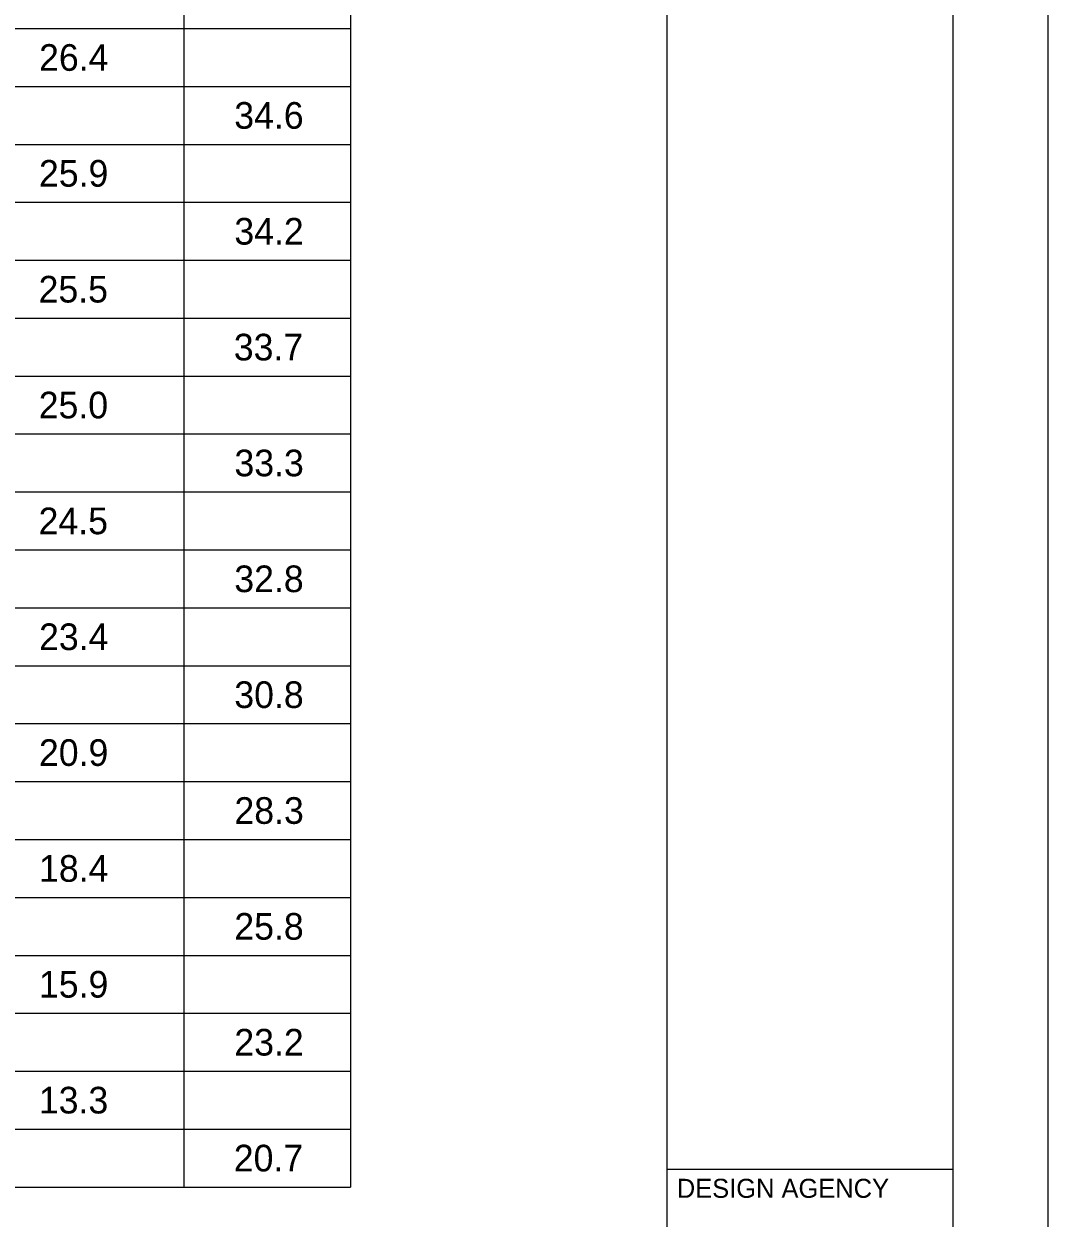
# Model space of a CAD drawing. Extents: x 0 to 34, y 0 to 22.
# Drawn here: x 28.62 to 34, y 4.24 to 10.52 of the extents above; entities that cross this region are included whole.
import ezdxf

# ---------------------------------------------------------------- set-up
doc = ezdxf.new("R2010")
doc.units = 0
for name, color, linetype in [('BR_P_Gen_Text', 7, 'Continuous'), ('SH_Border', 7, 'Continuous'), ('SH_Cut_Line', 7, 'Continuous'), ('SH_Data', 7, 'Continuous')]:
    doc.layers.add(name, color=color, linetype=linetype)

msp = doc.modelspace()

# ---------------------------------------------------------------- linework, layer by layer
at = {"layer": 'BR_P_Gen_Text'}
for p, q in [((30.3354, 21.1204), (30.3354, 4.4066)), ((29.4604, 20.7019), (29.4604, 4.4066)), ((22.1053, 10.4936), (30.3354, 10.4936)), ((22.1053, 10.1893), (30.3354, 10.1893)), ((22.1053, 9.8849), (30.3354, 9.8849)), ((22.1053, 9.5806), (30.3354, 9.5806)), ((22.1053, 9.2762), (30.3354, 9.2762)), ((22.1053, 8.9719), (30.3354, 8.9719)), ((22.1053, 8.6675), (30.3354, 8.6675)), ((22.1053, 8.3632), (30.3354, 8.3632)), ((22.1053, 8.0588), (30.3354, 8.0588)), ((22.1053, 7.7545), (30.3354, 7.7545)), ((22.1053, 7.4501), (30.3354, 7.4501)), ((22.1053, 7.1458), (30.3354, 7.1458)), ((22.1053, 6.8414), (30.3354, 6.8414)), ((22.1053, 6.5371), (30.3354, 6.5371)), ((22.1053, 6.2327), (30.3354, 6.2327)), ((22.1053, 5.9284), (30.3354, 5.9284)), ((22.1053, 5.624), (30.3354, 5.624)), ((22.1053, 5.3197), (30.3354, 5.3197)), ((22.1053, 5.0153), (30.3354, 5.0153)), ((22.1053, 4.711), (30.3354, 4.711)), ((22.1053, 4.4066), (30.3354, 4.4066))]:
    msp.add_line(p, q, dxfattribs=at)
at = {"layer": 'SH_Border'}
for p, q in [((32, 0.5), (32, 21.5)), ((32, 4.5), (33.5, 4.5))]:
    msp.add_line(p, q, dxfattribs=at)
msp.add_lwpolyline([(1.5, 21.5), (33.5, 21.5), (33.5, 0.5), (1.5, 0.5)], close=True, dxfattribs=at)
at = {"layer": 'SH_Cut_Line'}
msp.add_lwpolyline([(0, 0), (34, 0), (34, 22), (0, 22)], close=True, dxfattribs=at)

# ---------------------------------------------------------------- texts
at = {"layer": 'BR_P_Gen_Text'}
for s, p in [('26.4', (28.7005, 10.2714)), ('34.6', (29.7256, 9.9671)), ('25.9', (28.6999, 9.6627)), ('34.2', (29.7261, 9.3584)), ('25.5', (28.698, 9.054)), ('33.7', (29.7232, 8.7497)), ('25.0', (28.6987, 8.4453)), ('33.3', (29.7266, 8.141)), ('24.5', (28.698, 7.8366)), ('32.8', (29.7259, 7.5323)), ('23.4', (28.7005, 7.2279)), ('30.8', (29.7259, 6.9236)), ('20.9', (28.6999, 6.6193)), ('28.3', (29.7266, 6.3149)), ('18.4', (28.7005, 6.0106)), ('25.8', (29.7259, 5.7062)), ('15.9', (28.6999, 5.4019)), ('23.2', (29.7261, 5.0975)), ('13.3', (28.6994, 4.7932)), ('20.7', (29.7232, 4.4888))]:
    msp.add_text(s, height=0.14, dxfattribs=at).set_placement(p)
at = {"layer": 'SH_Data'}
msp.add_text('DESIGN AGENCY', height=0.1, dxfattribs=at).set_placement((32.05, 4.35))

doc.saveas('drawing.dxf')
